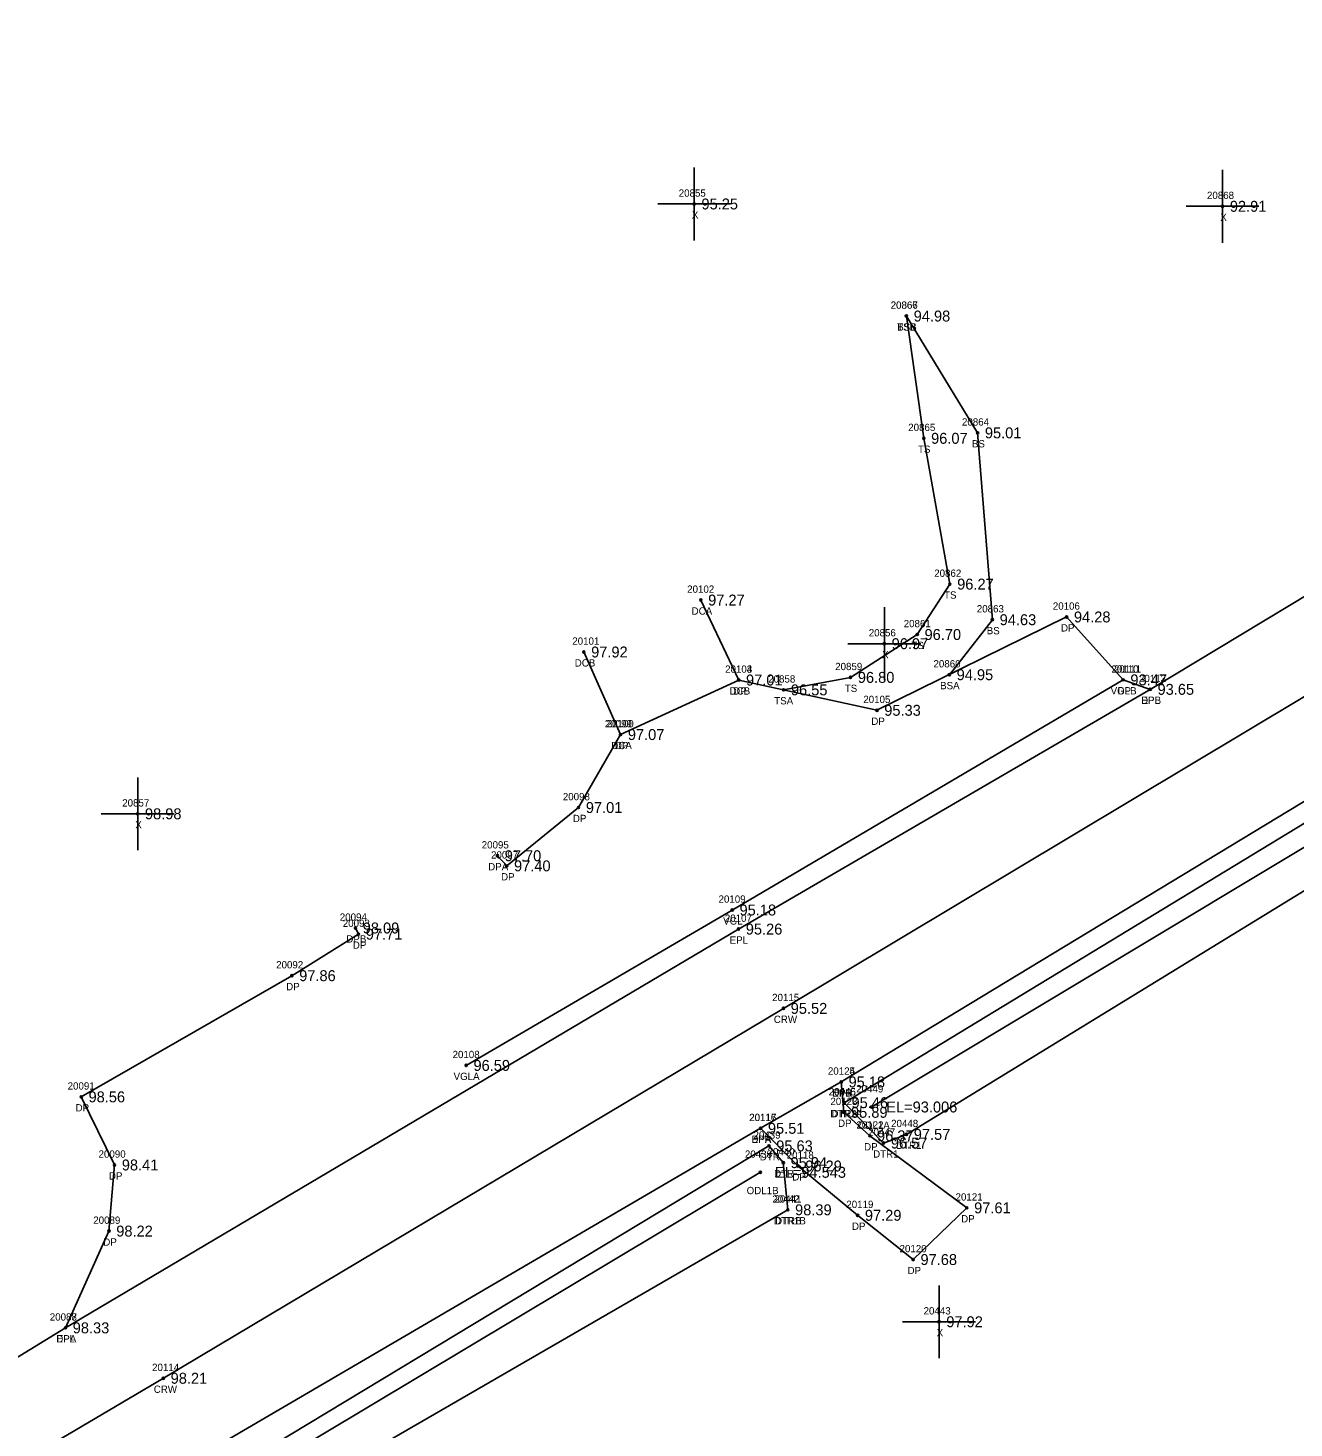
# Model space of a CAD drawing. Extents: x 2530197 to 2532051, y 935230 to 936631.
# Drawn here: x 2530770.7 to 2530944.6, y 935755.5 to 935947.8 of the extents above; entities that cross this region are included whole.
import ezdxf

# ---------------------------------------------------------------- set-up
doc = ezdxf.new("R2010")
doc.units = 0
for name, color, linetype in [('RD_DTM_BkLn1', 7, 'Continuous'), ('RD_DTM_BkLn2', 7, 'Continuous'), ('RD_DTM_BkLn_txCode', 7, 'Continuous'), ('RD_EX_Conc', 7, 'Continuous'), ('RD_EX_Conc_txCode', 7, 'Continuous'), ('RD_EX_Driveway', 7, 'Continuous'), ('RD_EX_Driveway_txCode', 7, 'Continuous'), ('RD_EX_H2O', 7, 'Continuous'), ('RD_EX_H2O_txCode', 7, 'Continuous'), ('RD_EX_Misc', 7, 'Continuous'), ('RD_EX_Misc_txCode', 7, 'Continuous'), ('RD_EX_Road', 7, 'Continuous'), ('RD_EX_Road_txCode', 7, 'Continuous'), ('RD_EX_TX_Conc_ELEV', 7, 'Continuous'), ('RD_EX_TX_Driveway_ELEV', 7, 'Continuous'), ('RD_EX_TX_H2O_ELEV', 7, 'Continuous'), ('RD_EX_TX_Misc_ELEV', 7, 'Continuous'), ('RD_EX_TX_Road_ELEV', 7, 'Continuous'), ('RD_HC_Survey_ELEV', 7, 'Continuous'), ('RD_HC_Survey_txCode', 7, 'Continuous'), ('RD_SMD_Locator', 7, 'Continuous')]:
    doc.layers.add(name, color=color, linetype=linetype)

msp = doc.modelspace()

# ---------------------------------------------------------------- linework, layer by layer
at = {"layer": 'RD_DTM_BkLn1'}
msp.add_lwpolyline([(2530212.5, 935590.24), (2530312.97, 935590.25), (2530414.21, 935590.57), (2530470.01, 935593.88), (2530526.51, 935611.77), (2530574.01, 935635.84), (2530615.35, 935659.73), (2530701.7, 935710.7), (2530789.3, 935762.35), (2530874.46, 935813.14), (2530961.78, 935865.4), (2531046.63, 935916.04), (2531084.76, 935938.51)], dxfattribs=at)
at = {"layer": 'RD_DTM_BkLn2'}
for points in [[(2530874.49, 935856.88), (2530883.68, 935858.59), (2530892.84, 935864.48), (2530897.32, 935871.4), (2530893.74, 935891.42), (2530891.35, 935908.21)], [(2530897.25, 935858.96), (2530903.16, 935866.51), (2530901.13, 935892.17), (2530891.35, 935908.21)]]:
    msp.add_lwpolyline(points, dxfattribs=at)
at = {"layer": 'RD_EX_Conc'}
for p, q in [((2530863.12, 935869.21), (2530868.32, 935858.23)), ((2530852.09, 935850.74), (2530847.05, 935862.08))]:
    msp.add_line(p, q, dxfattribs=at)
at = {"layer": 'RD_EX_Driveway'}
for points in [[(2530835.18, 935834.1), (2530836.46, 935832.71), (2530846.32, 935840.72), (2530852.09, 935850.74), (2530868.32, 935858.23), (2530887.31, 935854.07), (2530913.36, 935866.89), (2530921.11, 935858.25), (2530924.84, 935856.95)], [(2530775.85, 935769.27), (2530781.83, 935782.56), (2530782.59, 935791.64), (2530778.02, 935800.99), (2530806.95, 935817.63), (2530816.1, 935823.33), (2530815.68, 935824.18)], [(2530871.33, 935796.67), (2530876.46, 935791.5), (2530884.65, 935784.73), (2530892.28, 935778.65), (2530899.65, 935785.75), (2530886.32, 935795.64), (2530882.74, 935798.87), (2530882.4, 935803.04)]]:
    msp.add_lwpolyline(points, dxfattribs=at)
at = {"layer": 'RD_EX_H2O'}
msp.add_line((2530886.58, 935799.6), (2530948.95, 935837.06), dxfattribs=at)
for points in [[(2530882.81, 935800.19), (2530949.87, 935840.9), (2530952.69, 935838.3), (2530953.21, 935833.74)], [(2530882.81, 935800.19), (2530888.21, 935794.65), (2530891.36, 935795.84), (2530953.21, 935833.74)], [(2530722.38, 935704.62), (2530796.68, 935748.53), (2530872.47, 935794.26), (2530874.44, 935791.96), (2530875.06, 935785.48)], [(2530724.37, 935703.48), (2530797.51, 935746.5), (2530871.29, 935790.63)], [(2530722.38, 935704.62), (2530722.37, 935702.56), (2530725.17, 935700.81), (2530799.94, 935742.04), (2530875.06, 935785.48)]]:
    msp.add_lwpolyline(points, dxfattribs=at)
at = {"layer": 'RD_EX_Misc'}
for p, q in [((2530862.2, 935918.6), (2530862.2, 935928.6)), ((2530934.77, 935918.28), (2530934.77, 935928.28)), ((2530857.2, 935923.6), (2530867.2, 935923.6)), ((2530929.77, 935923.28), (2530939.77, 935923.28)), ((2530888.32, 935858.22), (2530888.32, 935868.22)), ((2530883.32, 935863.22), (2530893.32, 935863.22)), ((2530785.77, 935834.86), (2530785.77, 935844.86)), ((2530780.77, 935839.86), (2530790.77, 935839.86)), ((2530895.83, 935765.11), (2530895.83, 935775.11)), ((2530890.83, 935770.11), (2530900.83, 935770.11))]:
    msp.add_line(p, q, dxfattribs=at)
at = {"layer": 'RD_EX_Road'}
for points in [[(2530213.13, 935600.16), (2530313.8, 935600.81), (2530414.15, 935601.13), (2530426.72, 935601.43), (2530429.46, 935603.55), (2530467.67, 935608.62), (2530486.46, 935612.38), (2530518.02, 935622.55), (2530522.16, 935623.68), (2530567.91, 935646.01), (2530609.3, 935670.15), (2530695.46, 935720.02), (2530775.85, 935769.27), (2530868.29, 935824.03), (2530924.84, 935856.95), (2530956.21, 935875.82), (2531040.72, 935926.38), (2531079.45, 935947.76)], [(2530212.44, 935579.72), (2530312.61, 935580.14), (2530402.98, 935580.64), (2530451.06, 935579.53), (2530466.91, 935580.35), (2530487.45, 935583.29), (2530533.43, 935598.45), (2530580.28, 935625.08), (2530621.69, 935649.23), (2530704.62, 935698.35), (2530718.67, 935706.38), (2530795.45, 935752.36), (2530871.33, 935796.67), (2530882.4, 935803.04), (2530947.17, 935842.26), (2530966, 935852.42), (2530992.72, 935868), (2531009.49, 935879.01), (2531052.39, 935904.85), (2531090.88, 935928.23)], [(2530830.89, 935805.31), (2530867.43, 935826.65), (2530921.11, 935858.25)]]:
    msp.add_lwpolyline(points, dxfattribs=at)
at = {"layer": 'RD_SMD_Locator'}
for centre in [(2530862.2, 935923.6), (2530934.77, 935923.28), (2530891.35, 935908.21), (2530891.35, 935908.21), (2530901.13, 935892.17), (2530893.74, 935891.42), (2530897.32, 935871.4), (2530863.12, 935869.21), (2530913.36, 935866.89), (2530903.16, 935866.51), (2530888.32, 935863.22), (2530892.84, 935864.48), (2530847.05, 935862.08), (2530897.25, 935858.96), (2530868.32, 935858.23), (2530868.32, 935858.23), (2530883.68, 935858.59), (2530921.11, 935858.25), (2530921.11, 935858.25), (2530924.84, 935856.95), (2530924.84, 935856.95), (2530874.49, 935856.88), (2530887.31, 935854.07), (2530852.09, 935850.74), (2530852.09, 935850.74), (2530785.77, 935839.86), (2530846.32, 935840.72), (2530835.18, 935834.1), (2530836.46, 935832.71), (2530867.43, 935826.65), (2530815.68, 935824.18), (2530816.1, 935823.33), (2530868.29, 935824.03), (2530806.95, 935817.63), (2530874.46, 935813.14), (2530830.89, 935805.31), (2530882.4, 935803.04), (2530882.4, 935803.04), (2530778.02, 935800.99), (2530882.81, 935800.19), (2530882.81, 935800.19), (2530886.58, 935799.6), (2530882.74, 935798.87), (2530871.33, 935796.67), (2530871.33, 935796.67), (2530886.32, 935795.64), (2530891.36, 935795.84), (2530872.47, 935794.26), (2530888.21, 935794.65), (2530782.59, 935791.64), (2530874.44, 935791.96), (2530871.29, 935790.63), (2530876.46, 935791.5), (2530875.06, 935785.48), (2530875.06, 935785.48), (2530884.65, 935784.73), (2530899.65, 935785.75), (2530781.83, 935782.56), (2530892.28, 935778.65), (2530775.85, 935769.27), (2530775.85, 935769.27), (2530895.83, 935770.11), (2530789.3, 935762.35)]:
    msp.add_circle(centre, 0.15, dxfattribs=at)

# ---------------------------------------------------------------- texts
at = {"layer": 'RD_DTM_BkLn_txCode'}
for s, p in [('20866', (2530889.18, 935909.21)), ('20867', (2530889.2, 935909.21)), ('TSB', (2530890.08, 935906.21)), ('BSB', (2530890.09, 935906.21)), ('20864', (2530898.98, 935893.17)), ('20865', (2530891.6, 935892.42)), ('TS', (2530892.94, 935889.42)), ('BS', (2530900.35, 935890.17)), ('20862', (2530895.17, 935872.4)), ('TS', (2530896.52, 935869.4)), ('20863', (2530901.02, 935867.51)), ('20861', (2530890.98, 935865.48)), ('BS', (2530902.38, 935864.51)), ('TS', (2530892.04, 935862.48)), ('20860', (2530895.07, 935859.96)), ('20859', (2530881.57, 935859.59)), ('20858', (2530872.37, 935857.88)), ('TS', (2530882.89, 935856.59)), ('BSA', (2530895.98, 935856.96)), ('TSA', (2530873.2, 935854.88))]:
    msp.add_text(s, height=1, dxfattribs=at).set_placement(p)
at = {"layer": 'RD_EX_Conc_txCode'}
for s, p in [('20102', (2530861.24, 935870.21)), ('DCA', (2530861.85, 935867.21)), ('20101', (2530845.46, 935863.08)), ('DCB', (2530845.8, 935860.08)), ('20103', (2530866.45, 935859.23)), ('DCB', (2530867.07, 935856.23)), ('20100', (2530850.18, 935851.74)), ('DCA', (2530850.82, 935848.74))]:
    msp.add_text(s, height=1, dxfattribs=at).set_placement(p)
at = {"layer": 'RD_EX_Driveway_txCode'}
for s, p in [('20106', (2530911.46, 935867.89)), ('DP', (2530912.58, 935864.89)), ('20104', (2530866.45, 935859.23)), ('20111', (2530919.85, 935859.25)), ('DP', (2530867.54, 935856.23)), ('DP', (2530920.34, 935856.25)), ('20112', (2530923.29, 935857.95)), ('20105', (2530885.43, 935855.07)), ('DPB', (2530923.58, 935854.95)), ('20099', (2530849.93, 935851.74)), ('DP', (2530886.53, 935852.07)), ('DP', (2530851.31, 935848.74)), ('20098', (2530844.16, 935841.72)), ('DP', (2530845.54, 935838.72)), ('20095', (2530833.02, 935835.1)), ('20097', (2530834.3, 935833.71)), ('DPA', (2530833.91, 935832.1)), ('DP', (2530835.68, 935830.71)), ('20094', (2530813.53, 935825.18)), ('20093', (2530813.94, 935824.33)), ('DPB', (2530814.43, 935822.18)), ('DP', (2530815.32, 935821.33)), ('20092', (2530804.79, 935818.63)), ('DP', (2530806.17, 935815.63)), ('20124', (2530880.57, 935804.04)), ('20091', (2530776.15, 935801.99)), ('DPB', (2530881.15, 935801.04)), ('DP', (2530777.24, 935798.99)), ('20123', (2530880.91, 935799.87)), ('20117', (2530869.78, 935797.67)), ('DP', (2530881.96, 935796.87)), ('20122', (2530884.49, 935796.64)), ('DPA', (2530870.06, 935794.67)), ('20090', (2530780.4, 935792.64)), ('DP', (2530885.54, 935793.64)), ('20118', (2530874.91, 935792.5)), ('DP', (2530781.82, 935789.64)), ('DP', (2530875.68, 935789.5)), ('20119', (2530883.1, 935785.73)), ('20121', (2530898.1, 935786.75)), ('20089', (2530779.67, 935783.56)), ('DP', (2530898.87, 935783.75)), ('DP', (2530883.87, 935782.73)), ('DP', (2530781.05, 935780.56)), ('20120', (2530890.41, 935779.65)), ('DP', (2530891.5, 935776.65)), ('20088', (2530773.7, 935770.27)), ('DPA', (2530774.59, 935767.27))]:
    msp.add_text(s, height=1, dxfattribs=at).set_placement(p)
at = {"layer": 'RD_EX_H2O_txCode'}
for s, p in [('20446', (2530880.67, 935801.19)), ('20445', (2530880.7, 935801.19)), ('20449', (2530884.46, 935801.6)), ('DTR1A', (2530880.89, 935798.19)), ('DTRA', (2530881.06, 935798.19)), ('ODL1A', (2530884.68, 935796.6)), ('20448', (2530889.25, 935796.84)), ('20439', (2530870.35, 935795.26)), ('20447', (2530886.09, 935795.65)), ('20438', (2530869.17, 935792.63)), ('20440', (2530872.28, 935792.96)), ('DTR1', (2530886.78, 935792.65)), ('DTR1', (2530889.93, 935793.84)), ('DTR', (2530871.21, 935792.26)), ('DTR', (2530873.17, 935789.96)), ('ODL1B', (2530869.41, 935787.63)), ('20442', (2530872.95, 935786.48)), ('20441', (2530873.23, 935786.48)), ('DTR1B', (2530873.16, 935783.48)), ('DTRB', (2530873.32, 935783.48))]:
    msp.add_text(s, height=1, dxfattribs=at).set_placement(p)
at = {"layer": 'RD_EX_Misc_txCode'}
for s, p in [('20855', (2530860.08, 935924.6)), ('20868', (2530932.63, 935924.28)), ('X', (2530861.89, 935921.6)), ('X', (2530934.46, 935921.28)), ('20856', (2530886.18, 935864.22)), ('X', (2530888.01, 935861.22)), ('20857', (2530783.65, 935840.86)), ('X', (2530785.45, 935837.86)), ('20443', (2530893.71, 935771.11)), ('X', (2530895.51, 935768.11))]:
    msp.add_text(s, height=1, dxfattribs=at).set_placement(p)
at = {"layer": 'RD_EX_Road_txCode'}
for s, p in [('20110', (2530919.52, 935859.25)), ('VGLB', (2530919.4, 935856.25)), ('20113', (2530923.29, 935857.95)), ('EPL', (2530923.63, 935854.95)), ('20109', (2530865.55, 935827.65)), ('VGL', (2530866.18, 935824.65)), ('20107', (2530866.41, 935825.03)), ('EPL', (2530867.08, 935822.03)), ('20108', (2530829.02, 935806.31)), ('VGLA', (2530829.16, 935803.31)), ('20125', (2530880.57, 935804.04)), ('EPR', (2530881.18, 935801.04)), ('20116', (2530869.75, 935797.67)), ('EPR', (2530870.1, 935794.67)), ('20087', (2530773.7, 935770.27)), ('EPL', (2530774.65, 935767.27))]:
    msp.add_text(s, height=1, dxfattribs=at).set_placement(p)
at = {"layer": 'RD_EX_TX_Conc_ELEV'}
for s, p in [('97.27', (2530864.12, 935868.46)), ('97.92', (2530848.05, 935861.33)), ('97.01', (2530869.32, 935857.48)), ('97.07', (2530853.09, 935849.99))]:
    msp.add_text(s, height=1.5, dxfattribs=at).set_placement(p)
at = {"layer": 'RD_EX_TX_Driveway_ELEV'}
for s, p in [('94.28', (2530914.36, 935866.14)), ('97.01', (2530869.32, 935857.48)), ('93.47', (2530922.11, 935857.5)), ('93.65', (2530925.84, 935856.2)), ('95.33', (2530888.31, 935853.32)), ('97.07', (2530853.09, 935849.99)), ('97.01', (2530847.32, 935839.97)), ('97.70', (2530836.18, 935833.35)), ('97.40', (2530837.46, 935831.96)), ('98.09', (2530816.68, 935823.43)), ('97.71', (2530817.1, 935822.58)), ('97.86', (2530807.95, 935816.88)), ('95.18', (2530883.4, 935802.29)), ('98.56', (2530779.02, 935800.24)), ('95.89', (2530883.74, 935798.12)), ('95.51', (2530872.33, 935795.92)), ('96.37', (2530887.32, 935794.89)), ('98.41', (2530783.59, 935790.89)), ('96.29', (2530877.46, 935790.75)), ('97.61', (2530900.65, 935785)), ('97.29', (2530885.65, 935783.98)), ('98.22', (2530782.83, 935781.81)), ('97.68', (2530893.28, 935777.9)), ('98.33', (2530776.85, 935768.52))]:
    msp.add_text(s, height=1.5, dxfattribs=at).set_placement(p)
at = {"layer": 'RD_EX_TX_H2O_ELEV'}
for s, p in [('95.46', (2530883.81, 935799.44)), ('95.46', (2530883.81, 935799.44)), ('EL=93.006', (2530888.58, 935798.85)), ('97.57', (2530892.36, 935795.09)), ('95.63', (2530873.47, 935793.51)), ('96.57', (2530889.21, 935793.9)), ('95.94', (2530875.44, 935791.21)), ('EL=94.543', (2530873.29, 935789.88)), ('98.39', (2530876.06, 935784.73)), ('98.39', (2530876.06, 935784.73))]:
    msp.add_text(s, height=1.5, dxfattribs=at).set_placement(p)
at = {"layer": 'RD_EX_TX_Misc_ELEV'}
for s, p in [('95.25', (2530863.2, 935922.85)), ('92.91', (2530935.77, 935922.53)), ('94.98', (2530892.35, 935907.46)), ('94.98', (2530892.35, 935907.46)), ('96.07', (2530894.74, 935890.67)), ('95.01', (2530902.13, 935891.42)), ('96.27', (2530898.32, 935870.65)), ('94.63', (2530904.16, 935865.76)), ('96.70', (2530893.84, 935863.73)), ('96.97', (2530889.32, 935862.47)), ('96.80', (2530884.68, 935857.84)), ('94.95', (2530898.25, 935858.21)), ('96.55', (2530875.49, 935856.13)), ('98.98', (2530786.77, 935839.11)), ('97.92', (2530896.83, 935769.36))]:
    msp.add_text(s, height=1.5, dxfattribs=at).set_placement(p)
at = {"layer": 'RD_EX_TX_Road_ELEV'}
for s, p in [('93.47', (2530922.11, 935857.5)), ('93.65', (2530925.84, 935856.2)), ('95.18', (2530868.43, 935825.9)), ('95.26', (2530869.29, 935823.28)), ('96.59', (2530831.89, 935804.56)), ('95.18', (2530883.4, 935802.29)), ('95.51', (2530872.33, 935795.92)), ('98.33', (2530776.85, 935768.52))]:
    msp.add_text(s, height=1.5, dxfattribs=at).set_placement(p)
at = {"layer": 'RD_HC_Survey_ELEV'}
for s, p in [('95.52', (2530875.46, 935812.39)), ('98.21', (2530790.3, 935761.6))]:
    msp.add_text(s, height=1.5, dxfattribs=at).set_placement(p)
at = {"layer": 'RD_HC_Survey_txCode'}
for s, p in [('20115', (2530872.91, 935814.14)), ('CRW', (2530873.14, 935811.14)), ('20114', (2530787.75, 935763.35)), ('CRW', (2530787.98, 935760.35))]:
    msp.add_text(s, height=1, dxfattribs=at).set_placement(p)

doc.saveas('drawing.dxf')
